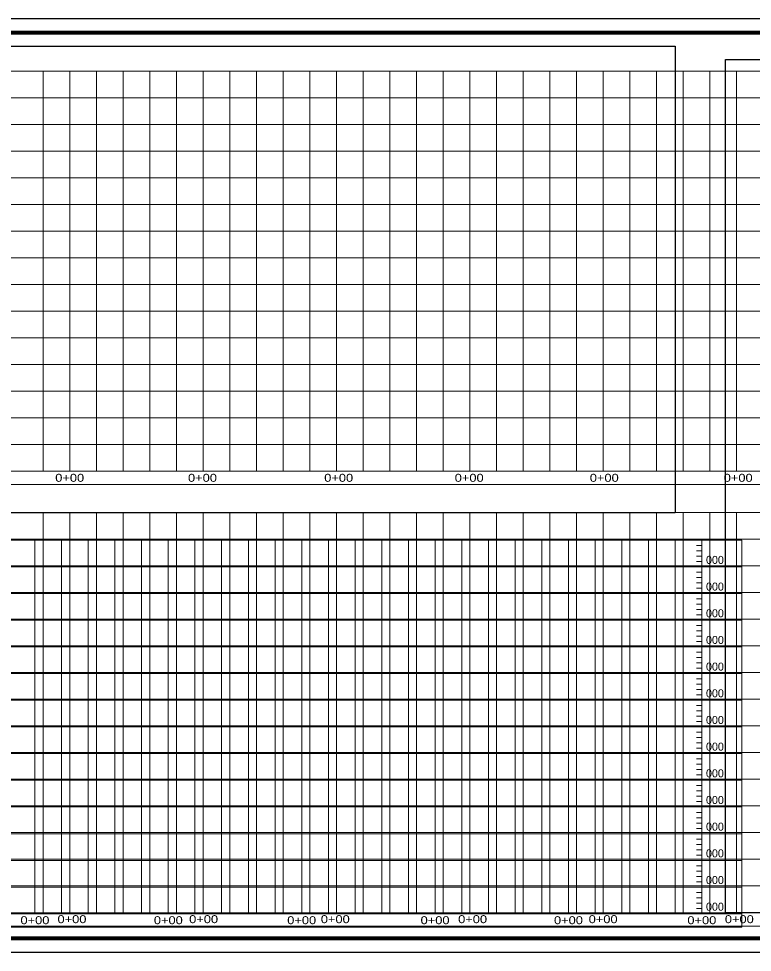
# Model space of a CAD drawing. Extents: x 2246932 to 2264252, y 7095151 to 7098651.
# Drawn here: x 2259900 to 2262650, y 7095151 to 7098651 of the extents above; entities that cross this region are included whole.
import ezdxf
from ezdxf.enums import TextEntityAlignment as Align

# ---------------------------------------------------------------- set-up
doc = ezdxf.new("R2010")
doc.units = 0
doc.header["$LTSCALE"] = 12
for name, color, linetype, lineweight in [('1', 7, 'Continuous', 80), ('2', 7, 'Continuous', 25), ('59', 7, 'Continuous', 13), ('60', 7, 'Continuous', 13), ('62', 7, 'Continuous', 13), ('63', 7, 'Continuous', 25)]:
    doc.layers.add(name, color=color, linetype=linetype, lineweight=lineweight)
doc.layers.add('22', color=7, linetype='Continuous')
doc.layers.add('23', color=7, linetype='Continuous')

msp = doc.modelspace()

# ---------------------------------------------------------------- linework, layer by layer
at = {"layer": '1'}
for p, q in [((2264052.09, 7098598.35), (2247157.09, 7098598.35)), ((2247157.09, 7095203.35), (2264052.09, 7095203.35))]:
    msp.add_line(p, q, dxfattribs=at)
at = {"layer": '1', "lineweight": 25}
msp.add_line((2247104.59, 7095150.85), (2264104.59, 7095150.85), dxfattribs=at)
msp.add_lwpolyline([(2264104.59, 7095150.85), (2264104.59, 7098650.85), (2247104.59, 7098650.85), (2247104.59, 7095150.85)], dxfattribs=at)
at = {"layer": '2'}
msp.add_line((2262610.97, 7095203.35), (2264052.08, 7095203.35), dxfattribs=at)
at = {"layer": '59'}
for p, q in [((2247310.97, 7096695.64), (2262610.97, 7096695.64)), ((2259960.97, 7096695.64), (2259960.97, 7095995.64)), ((2260060.97, 7096695.64), (2260060.97, 7095995.64)), ((2260160.97, 7096695.64), (2260160.97, 7095995.64)), ((2260260.97, 7096695.64), (2260260.97, 7095995.64)), ((2260360.97, 7096695.64), (2260360.97, 7095995.64)), ((2260460.97, 7096695.64), (2260460.97, 7095995.64)), ((2260560.97, 7096695.64), (2260560.97, 7095995.64)), ((2260660.97, 7096695.64), (2260660.97, 7095995.64)), ((2260760.97, 7096695.64), (2260760.97, 7095995.64)), ((2260860.97, 7096695.64), (2260860.97, 7095995.64)), ((2260960.97, 7096695.64), (2260960.97, 7095995.64)), ((2261060.97, 7096695.64), (2261060.97, 7095995.64)), ((2261160.97, 7096695.64), (2261160.97, 7095995.64)), ((2261260.97, 7096695.64), (2261260.97, 7095995.64)), ((2261360.97, 7096695.64), (2261360.97, 7095995.64)), ((2261460.97, 7096695.64), (2261460.97, 7095995.64)), ((2261560.97, 7096695.64), (2261560.97, 7095995.64)), ((2261660.97, 7096695.64), (2261660.97, 7095995.64)), ((2261760.97, 7096695.64), (2261760.97, 7095995.64)), ((2261860.97, 7096695.64), (2261860.97, 7095995.64)), ((2261960.97, 7096695.64), (2261960.97, 7095995.64)), ((2262060.97, 7096695.64), (2262060.97, 7095995.64)), ((2262160.97, 7096695.64), (2262160.97, 7095995.64)), ((2262260.97, 7096695.64), (2262260.97, 7095995.64)), ((2262360.97, 7096695.64), (2262360.97, 7095995.64)), ((2262460.97, 7096675.64), (2262440.97, 7096675.64)), ((2262460.97, 7095995.64), (2262460.97, 7096695.64)), ((2262610.97, 7096695.64), (2262610.97, 7095995.64)), ((2262460.97, 7096655.64), (2262440.97, 7096655.64)), ((2262460.97, 7096635.64), (2262440.97, 7096635.64)), ((2262460.97, 7096615.64), (2262440.97, 7096615.64)), ((2262460.97, 7096575.64), (2262440.97, 7096575.64)), ((2262460.97, 7096555.64), (2262440.97, 7096555.64)), ((2262460.97, 7096535.64), (2262440.97, 7096535.64)), ((2262460.97, 7096515.64), (2262440.97, 7096515.64)), ((2262460.97, 7096475.64), (2262440.97, 7096475.64)), ((2262460.97, 7096455.64), (2262440.97, 7096455.64)), ((2262460.97, 7096435.64), (2262440.97, 7096435.64)), ((2262460.97, 7096415.64), (2262440.97, 7096415.64)), ((2262460.97, 7096375.64), (2262440.97, 7096375.64)), ((2262460.97, 7096355.64), (2262440.97, 7096355.64)), ((2262460.97, 7096335.64), (2262440.97, 7096335.64)), ((2262460.97, 7096315.64), (2262440.97, 7096315.64)), ((2262460.97, 7096275.64), (2262440.97, 7096275.64)), ((2262460.97, 7096255.64), (2262440.97, 7096255.64)), ((2262460.97, 7096235.64), (2262440.97, 7096235.64)), ((2262460.97, 7096215.64), (2262440.97, 7096215.64)), ((2262460.97, 7096175.64), (2262440.97, 7096175.64)), ((2262460.97, 7096155.64), (2262440.97, 7096155.64)), ((2262460.97, 7096135.64), (2262440.97, 7096135.64)), ((2262460.97, 7096115.64), (2262440.97, 7096115.64)), ((2262460.97, 7096075.64), (2262440.97, 7096075.64)), ((2262460.97, 7096055.64), (2262440.97, 7096055.64)), ((2262460.97, 7096035.64), (2262440.97, 7096035.64)), ((2262460.97, 7096015.64), (2262440.97, 7096015.64)), ((2259960.97, 7095995.64), (2259960.97, 7095295.64)), ((2260060.97, 7095995.64), (2260060.97, 7095295.64)), ((2260160.97, 7095995.64), (2260160.97, 7095295.64)), ((2260260.97, 7095995.64), (2260260.97, 7095295.64)), ((2260360.97, 7095995.64), (2260360.97, 7095295.64)), ((2260460.97, 7095995.64), (2260460.97, 7095295.64)), ((2260560.97, 7095995.64), (2260560.97, 7095295.64)), ((2260660.97, 7095995.64), (2260660.97, 7095295.64)), ((2260760.97, 7095995.64), (2260760.97, 7095295.64)), ((2260860.97, 7095995.64), (2260860.97, 7095295.64)), ((2260960.97, 7095995.64), (2260960.97, 7095295.64)), ((2261060.97, 7095995.64), (2261060.97, 7095295.64)), ((2261160.97, 7095995.64), (2261160.97, 7095295.64)), ((2261260.97, 7095995.64), (2261260.97, 7095295.64)), ((2261360.97, 7095995.64), (2261360.97, 7095295.64)), ((2261460.97, 7095995.64), (2261460.97, 7095295.64)), ((2261560.97, 7095995.64), (2261560.97, 7095295.64)), ((2261660.97, 7095995.64), (2261660.97, 7095295.64)), ((2261760.97, 7095995.64), (2261760.97, 7095295.64)), ((2261860.97, 7095995.64), (2261860.97, 7095295.64)), ((2261960.97, 7095995.64), (2261960.97, 7095295.64)), ((2262060.97, 7095995.64), (2262060.97, 7095295.64)), ((2262160.97, 7095995.64), (2262160.97, 7095295.64)), ((2262260.97, 7095995.64), (2262260.97, 7095295.64)), ((2262360.97, 7095995.64), (2262360.97, 7095295.64)), ((2262460.97, 7095975.64), (2262440.97, 7095975.64)), ((2262460.97, 7095295.64), (2262460.97, 7095995.64)), ((2262610.97, 7095995.64), (2262610.97, 7095245.64)), ((2262460.97, 7095955.64), (2262440.97, 7095955.64)), ((2262460.97, 7095935.64), (2262440.97, 7095935.64)), ((2262460.97, 7095915.64), (2262440.97, 7095915.64)), ((2262460.97, 7095875.64), (2262440.97, 7095875.64)), ((2262460.97, 7095855.64), (2262440.97, 7095855.64)), ((2262460.97, 7095835.64), (2262440.97, 7095835.64)), ((2262460.97, 7095815.64), (2262440.97, 7095815.64)), ((2262460.97, 7095775.64), (2262440.97, 7095775.64)), ((2262460.97, 7095755.64), (2262440.97, 7095755.64)), ((2262460.97, 7095735.64), (2262440.97, 7095735.64)), ((2262460.97, 7095715.64), (2262440.97, 7095715.64)), ((2262460.97, 7095675.64), (2262440.97, 7095675.64)), ((2262460.97, 7095655.64), (2262440.97, 7095655.64)), ((2262460.97, 7095635.64), (2262440.97, 7095635.64)), ((2262460.97, 7095615.64), (2262440.97, 7095615.64)), ((2262460.97, 7095575.64), (2262440.97, 7095575.64)), ((2262460.97, 7095555.64), (2262440.97, 7095555.64)), ((2262460.97, 7095535.64), (2262440.97, 7095535.64)), ((2262460.97, 7095515.64), (2262440.97, 7095515.64)), ((2262460.97, 7095475.64), (2262440.97, 7095475.64)), ((2262460.97, 7095455.64), (2262440.97, 7095455.64)), ((2262460.97, 7095435.64), (2262440.97, 7095435.64)), ((2262460.97, 7095415.64), (2262440.97, 7095415.64)), ((2262460.97, 7095375.64), (2262440.97, 7095375.64)), ((2262460.97, 7095355.64), (2262440.97, 7095355.64)), ((2262460.97, 7095335.64), (2262440.97, 7095335.64)), ((2262460.97, 7095315.64), (2262440.97, 7095315.64)), ((2262610.97, 7095295.64), (2247310.97, 7095295.64)), ((2262610.97, 7095245.64), (2247310.97, 7095245.64))]:
    msp.add_line(p, q, dxfattribs=at)
for points in [[(2247460.97, 7096595.64), (2262460.97, 7096595.64), (2262610.97, 7096595.64)], [(2247460.97, 7096495.64), (2262460.97, 7096495.64), (2262610.97, 7096495.64)], [(2247460.97, 7096395.64), (2262460.97, 7096395.64), (2262610.97, 7096395.64)], [(2247460.97, 7096295.64), (2262460.97, 7096295.64), (2262610.97, 7096295.64)], [(2247460.97, 7096195.64), (2262460.97, 7096195.64), (2262610.97, 7096195.64)], [(2247454.92, 7096095.64), (2262460.97, 7096095.64), (2262610.97, 7096095.64)], [(2247460.97, 7095995.64), (2262460.97, 7095995.64), (2262610.97, 7095995.64)], [(2247460.97, 7095895.64), (2262460.97, 7095895.64), (2262610.97, 7095895.64)], [(2247460.97, 7095795.64), (2262460.97, 7095795.64), (2262610.97, 7095795.64)], [(2247460.97, 7095695.64), (2262460.97, 7095695.64), (2262610.97, 7095695.64)], [(2247460.97, 7095595.64), (2262460.97, 7095595.64), (2262610.97, 7095595.64)], [(2247460.97, 7095495.64), (2262460.97, 7095495.64), (2262610.97, 7095495.64)], [(2247460.97, 7095395.64), (2262460.97, 7095395.64), (2262610.97, 7095395.64)]]:
    msp.add_lwpolyline(points, dxfattribs=at)
at = {"layer": '60'}
for p, q in [((2252310.97, 7096695.64), (2262610.97, 7096695.64)), ((2259960.97, 7096695.64), (2259960.97, 7095995.64)), ((2260060.97, 7096695.64), (2260060.97, 7095995.64)), ((2260160.97, 7096695.64), (2260160.97, 7095995.64)), ((2260260.97, 7096695.64), (2260260.97, 7095995.64)), ((2260360.97, 7096695.64), (2260360.97, 7095995.64)), ((2260460.97, 7096695.64), (2260460.97, 7095995.64)), ((2260560.97, 7096695.64), (2260560.97, 7095995.64)), ((2260660.97, 7096695.64), (2260660.97, 7095995.64)), ((2260760.97, 7096695.64), (2260760.97, 7095995.64)), ((2260860.97, 7096695.64), (2260860.97, 7095995.64)), ((2260960.97, 7096695.64), (2260960.97, 7095995.64)), ((2261060.97, 7096695.64), (2261060.97, 7095995.64)), ((2261160.97, 7096695.64), (2261160.97, 7095995.64)), ((2261260.97, 7096695.64), (2261260.97, 7095995.64)), ((2261360.97, 7096695.64), (2261360.97, 7095995.64)), ((2261460.97, 7096695.64), (2261460.97, 7095995.64)), ((2261560.97, 7096695.64), (2261560.97, 7095995.64)), ((2261660.97, 7096695.64), (2261660.97, 7095995.64)), ((2261760.97, 7096695.64), (2261760.97, 7095995.64)), ((2261860.97, 7096695.64), (2261860.97, 7095995.64)), ((2261960.97, 7096695.64), (2261960.97, 7095995.64)), ((2262060.97, 7096695.64), (2262060.97, 7095995.64)), ((2262160.97, 7096695.64), (2262160.97, 7095995.64)), ((2262260.97, 7096695.64), (2262260.97, 7095995.64)), ((2262360.97, 7096695.64), (2262360.97, 7095995.64)), ((2262460.97, 7096675.64), (2262440.97, 7096675.64)), ((2262460.97, 7095995.64), (2262460.97, 7096695.64)), ((2262610.97, 7096695.64), (2262610.97, 7095995.64)), ((2262460.97, 7096655.64), (2262440.97, 7096655.64)), ((2262460.97, 7096635.64), (2262440.97, 7096635.64)), ((2262460.97, 7096615.64), (2262440.97, 7096615.64)), ((2262460.97, 7096575.64), (2262440.97, 7096575.64)), ((2262460.97, 7096555.64), (2262440.97, 7096555.64)), ((2262460.97, 7096535.64), (2262440.97, 7096535.64)), ((2262460.97, 7096515.64), (2262440.97, 7096515.64)), ((2262460.97, 7096475.64), (2262440.97, 7096475.64)), ((2262460.97, 7096455.64), (2262440.97, 7096455.64)), ((2262460.97, 7096435.64), (2262440.97, 7096435.64)), ((2262460.97, 7096415.64), (2262440.97, 7096415.64)), ((2262460.97, 7096375.64), (2262440.97, 7096375.64)), ((2262460.97, 7096355.64), (2262440.97, 7096355.64)), ((2262460.97, 7096335.64), (2262440.97, 7096335.64)), ((2262460.97, 7096315.64), (2262440.97, 7096315.64)), ((2262460.97, 7096275.64), (2262440.97, 7096275.64)), ((2262460.97, 7096255.64), (2262440.97, 7096255.64)), ((2262460.97, 7096235.64), (2262440.97, 7096235.64)), ((2262460.97, 7096215.64), (2262440.97, 7096215.64)), ((2262460.97, 7096175.64), (2262440.97, 7096175.64)), ((2262460.97, 7096155.64), (2262440.97, 7096155.64)), ((2262460.97, 7096135.64), (2262440.97, 7096135.64)), ((2262460.97, 7096115.64), (2262440.97, 7096115.64)), ((2262460.97, 7096075.64), (2262440.97, 7096075.64)), ((2262460.97, 7096055.64), (2262440.97, 7096055.64)), ((2262460.97, 7096035.64), (2262440.97, 7096035.64)), ((2262460.97, 7096015.64), (2262440.97, 7096015.64)), ((2259960.97, 7095995.64), (2259960.97, 7095295.64)), ((2260060.97, 7095995.64), (2260060.97, 7095295.64)), ((2260160.97, 7095995.64), (2260160.97, 7095295.64)), ((2260260.97, 7095995.64), (2260260.97, 7095295.64)), ((2260360.97, 7095995.64), (2260360.97, 7095295.64)), ((2260460.97, 7095995.64), (2260460.97, 7095295.64)), ((2260560.97, 7095995.64), (2260560.97, 7095295.64)), ((2260660.97, 7095995.64), (2260660.97, 7095295.64)), ((2260760.97, 7095995.64), (2260760.97, 7095295.64)), ((2260860.97, 7095995.64), (2260860.97, 7095295.64)), ((2260960.97, 7095995.64), (2260960.97, 7095295.64)), ((2261060.97, 7095995.64), (2261060.97, 7095295.64)), ((2261160.97, 7095995.64), (2261160.97, 7095295.64)), ((2261260.97, 7095995.64), (2261260.97, 7095295.64)), ((2261360.97, 7095995.64), (2261360.97, 7095295.64)), ((2261460.97, 7095995.64), (2261460.97, 7095295.64)), ((2261560.97, 7095995.64), (2261560.97, 7095295.64)), ((2261660.97, 7095995.64), (2261660.97, 7095295.64)), ((2261760.97, 7095995.64), (2261760.97, 7095295.64)), ((2261860.97, 7095995.64), (2261860.97, 7095295.64)), ((2261960.97, 7095995.64), (2261960.97, 7095295.64)), ((2262060.97, 7095995.64), (2262060.97, 7095295.64)), ((2262160.97, 7095995.64), (2262160.97, 7095295.64)), ((2262260.97, 7095995.64), (2262260.97, 7095295.64)), ((2262360.97, 7095995.64), (2262360.97, 7095295.64)), ((2262460.97, 7095975.64), (2262440.97, 7095975.64)), ((2262460.97, 7095295.64), (2262460.97, 7095995.64)), ((2262610.97, 7095995.64), (2262610.97, 7095245.64)), ((2262460.97, 7095955.64), (2262440.97, 7095955.64)), ((2262460.97, 7095935.64), (2262440.97, 7095935.64)), ((2262460.97, 7095915.64), (2262440.97, 7095915.64)), ((2262460.97, 7095875.64), (2262440.97, 7095875.64)), ((2262460.97, 7095855.64), (2262440.97, 7095855.64)), ((2262460.97, 7095835.64), (2262440.97, 7095835.64)), ((2262460.97, 7095815.64), (2262440.97, 7095815.64)), ((2262460.97, 7095775.64), (2262440.97, 7095775.64)), ((2262460.97, 7095755.64), (2262440.97, 7095755.64)), ((2262460.97, 7095735.64), (2262440.97, 7095735.64)), ((2262460.97, 7095715.64), (2262440.97, 7095715.64)), ((2262460.97, 7095675.64), (2262440.97, 7095675.64)), ((2262460.97, 7095655.64), (2262440.97, 7095655.64)), ((2262460.97, 7095635.64), (2262440.97, 7095635.64)), ((2262460.97, 7095615.64), (2262440.97, 7095615.64)), ((2262460.97, 7095575.64), (2262440.97, 7095575.64)), ((2262460.97, 7095555.64), (2262440.97, 7095555.64)), ((2262460.97, 7095535.64), (2262440.97, 7095535.64)), ((2262460.97, 7095515.64), (2262440.97, 7095515.64)), ((2262460.97, 7095475.64), (2262440.97, 7095475.64)), ((2262460.97, 7095455.64), (2262440.97, 7095455.64)), ((2262460.97, 7095435.64), (2262440.97, 7095435.64)), ((2262460.97, 7095415.64), (2262440.97, 7095415.64)), ((2262460.97, 7095375.64), (2262440.97, 7095375.64)), ((2262460.97, 7095355.64), (2262440.97, 7095355.64)), ((2262460.97, 7095335.64), (2262440.97, 7095335.64)), ((2262460.97, 7095315.64), (2262440.97, 7095315.64)), ((2262610.97, 7095295.64), (2252310.97, 7095295.64)), ((2262610.97, 7095245.64), (2252310.97, 7095245.64))]:
    msp.add_line(p, q, dxfattribs=at)
for points in [[(2252460.97, 7096595.64), (2262460.97, 7096595.64), (2262610.97, 7096595.64)], [(2252460.97, 7096495.64), (2262460.97, 7096495.64), (2262610.97, 7096495.64)], [(2252460.97, 7096395.64), (2262460.97, 7096395.64), (2262610.97, 7096395.64)], [(2252460.97, 7096295.64), (2262460.97, 7096295.64), (2262610.97, 7096295.64)], [(2252460.97, 7096195.64), (2262460.97, 7096195.64), (2262610.97, 7096195.64)], [(2252454.92, 7096095.64), (2262460.97, 7096095.64), (2262610.97, 7096095.64)], [(2252460.97, 7095995.64), (2262460.97, 7095995.64), (2262610.97, 7095995.64)], [(2252460.97, 7095895.64), (2262460.97, 7095895.64), (2262610.97, 7095895.64)], [(2252460.97, 7095795.64), (2262460.97, 7095795.64), (2262610.97, 7095795.64)], [(2252460.97, 7095695.64), (2262460.97, 7095695.64), (2262610.97, 7095695.64)], [(2252460.97, 7095595.64), (2262460.97, 7095595.64), (2262610.97, 7095595.64)], [(2252460.97, 7095495.64), (2262460.97, 7095495.64), (2262610.97, 7095495.64)], [(2252460.97, 7095395.64), (2262460.97, 7095395.64), (2262610.97, 7095395.64)]]:
    msp.add_lwpolyline(points, dxfattribs=at)
at = {"layer": '62'}
for p, q in [((2247941.45, 7098454.14), (2263241.45, 7098454.14)), ((2259991.45, 7098454.14), (2259991.45, 7096954.14)), ((2260091.45, 7098454.14), (2260091.45, 7096954.14)), ((2260191.45, 7098454.14), (2260191.45, 7096954.14)), ((2260291.45, 7098454.14), (2260291.45, 7096954.14)), ((2260391.45, 7098454.14), (2260391.45, 7096954.14)), ((2260491.45, 7098454.14), (2260491.45, 7096954.14)), ((2260591.45, 7098454.14), (2260591.45, 7096954.14)), ((2260691.45, 7098454.14), (2260691.45, 7096954.14)), ((2260791.45, 7098454.14), (2260791.45, 7096954.14)), ((2260891.45, 7098454.14), (2260891.45, 7096954.14)), ((2260991.45, 7098454.14), (2260991.45, 7096954.14)), ((2261091.45, 7098454.14), (2261091.45, 7096954.14)), ((2261191.45, 7098454.14), (2261191.45, 7096954.14)), ((2261291.45, 7098454.14), (2261291.45, 7096954.14)), ((2261391.45, 7098454.14), (2261391.45, 7096954.14)), ((2261491.45, 7098454.14), (2261491.45, 7096954.14)), ((2261591.45, 7098454.14), (2261591.45, 7096954.14)), ((2261691.45, 7098454.14), (2261691.45, 7096954.14)), ((2261791.45, 7098454.14), (2261791.45, 7096954.14)), ((2261891.45, 7098454.14), (2261891.45, 7096954.14)), ((2261991.45, 7098454.14), (2261991.45, 7096954.14)), ((2262091.45, 7098454.14), (2262091.45, 7096954.14)), ((2262191.45, 7098454.14), (2262191.45, 7096954.14)), ((2262291.45, 7098454.14), (2262291.45, 7096954.14)), ((2262391.45, 7098454.14), (2262391.45, 7096954.14)), ((2262491.45, 7098454.14), (2262491.45, 7096954.14)), ((2262591.45, 7098454.14), (2262591.45, 7096954.14)), ((2263241.45, 7096954.14), (2247941.45, 7096954.14)), ((2263241.45, 7096904.14), (2247941.45, 7096904.14)), ((2247941.45, 7096799.51), (2263241.45, 7096799.51)), ((2259991.45, 7096799.51), (2259991.45, 7095299.51)), ((2260091.45, 7096799.51), (2260091.45, 7095299.51)), ((2260191.45, 7096799.51), (2260191.45, 7095299.51)), ((2260291.45, 7096799.51), (2260291.45, 7095299.51)), ((2260391.45, 7096799.51), (2260391.45, 7095299.51)), ((2260491.45, 7096799.51), (2260491.45, 7095299.51)), ((2260591.45, 7096799.51), (2260591.45, 7095299.51)), ((2260691.45, 7096799.51), (2260691.45, 7095299.51)), ((2260791.45, 7096799.51), (2260791.45, 7095299.51)), ((2260891.45, 7096799.51), (2260891.45, 7095299.51)), ((2260991.45, 7096799.51), (2260991.45, 7095299.51)), ((2261091.45, 7096799.51), (2261091.45, 7095299.51)), ((2261191.45, 7096799.51), (2261191.45, 7095299.51)), ((2261291.45, 7096799.51), (2261291.45, 7095299.51)), ((2261391.45, 7096799.51), (2261391.45, 7095299.51)), ((2261491.45, 7096799.51), (2261491.45, 7095299.51)), ((2261591.45, 7096799.51), (2261591.45, 7095299.51)), ((2261691.45, 7096799.51), (2261691.45, 7095299.51)), ((2261791.45, 7096799.51), (2261791.45, 7095299.51)), ((2261891.45, 7096799.51), (2261891.45, 7095299.51)), ((2261991.45, 7096799.51), (2261991.45, 7095299.51)), ((2262091.45, 7096799.51), (2262091.45, 7095299.51)), ((2262191.45, 7096799.51), (2262191.45, 7095299.51)), ((2262291.45, 7096799.51), (2262291.45, 7095299.51)), ((2262391.45, 7096799.51), (2262391.45, 7095299.51)), ((2262491.45, 7096799.51), (2262491.45, 7095299.51)), ((2262591.45, 7096799.51), (2262591.45, 7095299.51)), ((2263241.45, 7095299.51), (2247941.45, 7095299.51)), ((2263241.45, 7095249.51), (2247941.45, 7095249.51))]:
    msp.add_line(p, q, dxfattribs=at)
for points in [[(2248091.45, 7098354.14), (2263091.45, 7098354.14), (2263241.45, 7098354.14)], [(2248091.45, 7098254.14), (2263091.45, 7098254.14), (2263241.45, 7098254.14)], [(2248091.45, 7098154.14), (2263091.45, 7098154.14), (2263241.45, 7098154.14)], [(2248091.45, 7098054.14), (2263091.45, 7098054.14), (2263241.45, 7098054.14)], [(2248091.45, 7097954.14), (2263091.45, 7097954.14), (2263241.45, 7097954.14)], [(2248091.45, 7097854.14), (2263091.45, 7097854.14), (2263241.45, 7097854.14)], [(2248091.45, 7097754.14), (2263091.45, 7097754.14), (2263241.45, 7097754.14)], [(2248091.45, 7097654.14), (2263091.45, 7097654.14), (2263241.45, 7097654.14)], [(2248091.45, 7097554.14), (2263091.45, 7097554.14), (2263241.45, 7097554.14)], [(2248091.45, 7097454.14), (2263091.45, 7097454.14), (2263241.45, 7097454.14)], [(2248091.45, 7097354.14), (2263091.45, 7097354.14), (2263241.45, 7097354.14)], [(2248091.45, 7097254.14), (2263091.45, 7097254.14), (2263241.45, 7097254.14)], [(2248091.45, 7097154.14), (2263091.45, 7097154.14), (2263241.45, 7097154.14)], [(2248091.45, 7097054.14), (2263091.45, 7097054.14), (2263241.45, 7097054.14)], [(2248091.45, 7096699.51), (2263091.45, 7096699.51), (2263241.45, 7096699.51)], [(2248091.45, 7096599.51), (2263091.45, 7096599.51), (2263241.45, 7096599.51)], [(2248091.45, 7096499.51), (2263091.45, 7096499.51), (2263241.45, 7096499.51)], [(2248091.45, 7096399.51), (2263091.45, 7096399.51), (2263241.45, 7096399.51)], [(2248091.45, 7096299.51), (2263091.45, 7096299.51), (2263241.45, 7096299.51)], [(2248091.45, 7096199.51), (2263091.45, 7096199.51), (2263241.45, 7096199.51)], [(2248091.45, 7096099.51), (2263091.45, 7096099.51), (2263241.45, 7096099.51)], [(2248091.45, 7095999.51), (2263091.45, 7095999.51), (2263241.45, 7095999.51)], [(2248091.45, 7095899.51), (2263091.45, 7095899.51), (2263241.45, 7095899.51)], [(2248091.45, 7095799.51), (2263091.45, 7095799.51), (2263241.45, 7095799.51)], [(2248091.45, 7095699.51), (2263091.45, 7095699.51), (2263241.45, 7095699.51)], [(2248091.45, 7095599.51), (2263091.45, 7095599.51), (2263241.45, 7095599.51)], [(2248091.45, 7095499.51), (2263091.45, 7095499.51), (2263241.45, 7095499.51)], [(2248091.45, 7095399.51), (2263091.45, 7095399.51), (2263241.45, 7095399.51)]]:
    msp.add_lwpolyline(points, dxfattribs=at)
at = {"layer": '63'}
for points in [[(2252360.97, 7098548.06), (2262360.97, 7098548.06), (2262360.97, 7096798.06), (2252360.97, 7096798.06)], [(2264252.09, 7095298.54), (2262549.93, 7095298.54), (2262549.93, 7098498.04), (2264252.09, 7098498.04)]]:
    msp.add_lwpolyline(points, close=True, dxfattribs=at)

# ---------------------------------------------------------------- texts
at = {"layer": '22', "width": 1.2}
for p in [(2260091.28, 7096914.74), (2260589.07, 7096914.74), (2261099.63, 7096914.74), (2261588.91, 7096914.74), (2262095.21, 7096914.74), (2262597.26, 7096914.74), (2260099.79, 7095260.11), (2260593.33, 7095260.11), (2261086.86, 7095260.11), (2261601.67, 7095260.11), (2262090.96, 7095260.11), (2262601.51, 7095260.11)]:
    msp.add_text('0+00', height=30, dxfattribs=at).set_placement(p, align=Align.CENTER)
at = {"layer": '23'}
for p in [(2262476.66, 7096606.9), (2262476.66, 7096506.9), (2262476.66, 7096406.9), (2262476.66, 7096306.9), (2262476.66, 7096206.9), (2262476.66, 7096106.9), (2262476.66, 7096006.9), (2262476.66, 7095906.9), (2262476.66, 7095806.9), (2262476.66, 7095706.9), (2262476.66, 7095606.9), (2262476.66, 7095506.9), (2262476.66, 7095406.9), (2262476.66, 7095306.9)]:
    msp.add_text('000', height=30, dxfattribs=at).set_placement(p)
at = {"layer": '23', "width": 1.2}
for p in [(2259960.97, 7095256.23), (2260460.97, 7095256.23), (2260960.97, 7095256.23), (2261460.97, 7095256.23), (2261960.97, 7095256.23), (2262460.97, 7095256.23), (2262460.97, 7095256.23)]:
    msp.add_text('0+00', height=30, dxfattribs=at).set_placement(p, align=Align.CENTER)

doc.saveas('drawing.dxf')
